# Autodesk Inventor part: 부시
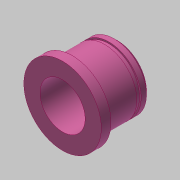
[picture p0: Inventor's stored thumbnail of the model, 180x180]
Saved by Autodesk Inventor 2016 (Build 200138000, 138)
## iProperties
Created: 2019-01
Part Number: 부시
Material: 강철, 연강
Document SubType Name: Modeling
Designer: mduedu
Density: 7.86 g/cm^3
Appearance: 분홍색
Mass: 23.9234 g
Surface Area: 24.4489 cm^2
Volume: 3.04369 cm^3
Author: mduedu
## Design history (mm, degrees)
sketch "스케치1"
  geometry: L1 (0, 0)-(3, 0); L2 (3, 0)-(3, 12); L3 (3, 12)-(0, 12); L4 (0, 12)-(0, 0); L5 (3, 0)-(17, 0); L6 (17, 0)-(17, 10); L7 (17, 10)-(3, 10); L8 (3, 10)-(3, 0)
  constraints: 16 end point, 4 parallel, 2 horizontal, 2 perpendicular
  dimensions: "d0" = 17 distance between parallel lines of L6 L4; "d2" = 3 distance of L2.end L3.end; "d3" = 24 diameter of L3 L1; "d4" = 20 diameter of L7 L5
revolve "회전1" sketch "스케치1" stored, may be unused: angle "d5" = 90 deg
sketch "스케치2"
  geometry: C1 r 7 at (0, 0); 1 further point
  constraints: 1 centre point, 1 coincident
  dimensions: "d6" = 14 diameter of C1
extrude "돌출1" cut sketch "스케치2" stored distance "d7" = 10; taper "d8" = 0 deg
chamfer "모따기1" distance "d9" = 1; stored, may be unused: second distance "d10" = 2, angle "d11" = 45 deg
node "작업 평면1"
sketch "스케치3"
  geometry: C1 r 9.5 at (0, 0); C2 r 10 at (0, 0) reference; 1 further point
  constraints: 1 centre point, 1 coincident
  dimensions: "d13" = 19 diameter of C1
extrude "돌출2" cut sketch "스케치3" distance "d14" = 1.35; taper "d15" = 0 deg
node "솔리드1"
